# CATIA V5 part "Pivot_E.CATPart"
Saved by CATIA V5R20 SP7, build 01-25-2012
Part number: Pivot_E
Bounding box of the stored display mesh (mm): x -2.5 to 2.5, y -2.5 to 2.5, z -6 to 6
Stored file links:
  D:\IFMA\COURS\2A\projet balance IAO\catia\Pivot_E.CATPart
  D:\IFMA\COURS\2A\projet balance IAO\catia\Ass_projet_balance.CATProduct
  D:\IFMA\COURS\2A\projet balance IAO\catia\Barre_HEG.CATPart
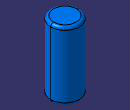
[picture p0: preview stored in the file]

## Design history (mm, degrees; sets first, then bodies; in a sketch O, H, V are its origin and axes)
Set1
  Plane1: linked copy from another document
  Point1 "Point.E": linked copy from another document
Body1 (main body)
  Sketch1 on Plane1, origin (0, 0, 0), H (1, 0, 0), V (0, 1, 0)
    circle A1 centre (0, 0) radius 2.5
    point P1 (0, 0)
    reference projected point E1 (0, 0) from Point1
    radius A1 = 2.5
    coincidence: P1 E1
  Pad1: profile Sketch1, direction (0, 0, 1), length 6, mirrored extent
  Fillet1: radius 0.5, on edge [face of Pad1 from Sketch1.A1 | end face of Pad1]; edge [start face of Pad1 | face of Pad1 from Sketch1.A1]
